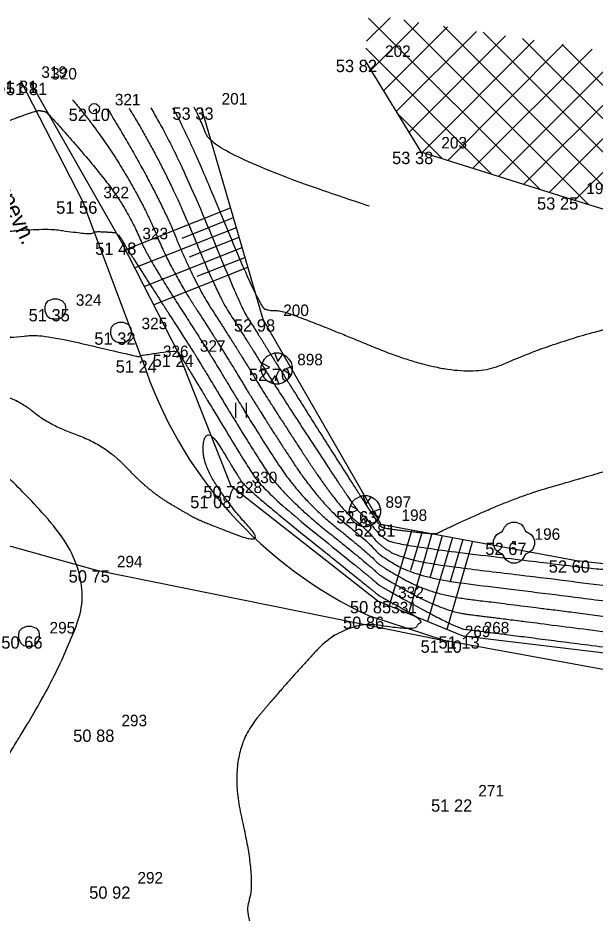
# Model space of a CAD drawing. Extents: x -704017 to -701500, y -1008977 to -1008450.
# Drawn here: x -703990.87 to -703976.82, y -1008655.12 to -1008633.32 of the extents above; entities that cross this region are included whole.
import ezdxf

# ---------------------------------------------------------------- set-up
doc = ezdxf.new("R2010")
doc.units = 0
for name, color, linetype in [('Z_body', 7, 'Continuous'), ('Z_body_cisla', 7, 'Continuous'), ('Z_body_vysky', 7, 'Continuous'), ('Z_komunikace', 7, 'Continuous'), ('Z_oploceni', 7, 'Continuous'), ('Z_popis', 7, 'Continuous'), ('Z_site_znaky_kanalizace', 7, 'Continuous'), ('Z_sloupky', 7, 'Continuous'), ('Z_teren_hrany_paty', 7, 'Continuous'), ('Z_vrstevnice_hlavni', 7, 'Continuous'), ('Z_vrstevnice_vedlejsi', 7, 'Continuous'), ('Z_zelen_jednotliva', 7, 'Continuous'), ('Z_zelen_souvisla_srafy', 7, 'Continuous')]:
    doc.layers.add(name, color=color, linetype=linetype)

# ---------------------------------------------------------------- blocks, each defined once
blk = doc.blocks.new('POINT_DISPLAY')
blk.add_line((0, 0), (0, 0))
blk = doc.blocks.new('Z306')
for p, q in [((-0.13, 0.17), (-0.13, -0.2)), ((0.13, 0.17), (0.13, -0.2))]:
    blk.add_line(p, q)
blk = doc.blocks.new('Z24')
for p, q in [((-0.23, 0.38), (-0.17, 0.45)), ((-0.17, 0.45), (-0.05, 0.5)), ((-0.05, 0.5), (0.05, 0.5)), ((0.05, 0.5), (0.17, 0.45)), ((0.17, 0.45), (0.23, 0.38)), ((-0.42, 0.2), (-0.28, 0.28)), ((-0.28, 0.28), (-0.23, 0.38)), ((0.23, 0.38), (0.28, 0.28)), ((0.28, 0.28), (0.42, 0.2)), ((-0.5, 0.05), (-0.47, 0.13)), ((-0.5, -0.05), (-0.5, 0.05)), ((-0.47, 0.13), (-0.42, 0.2)), ((-0.03, -0.03), (-0.03, 0.03)), ((-0.03, 0.03), (0.03, 0.03)), ((0.03, 0.03), (0.03, -0.03)), ((0.42, 0.2), (0.47, 0.13)), ((0.47, 0.13), (0.5, 0.05)), ((0.5, 0.05), (0.5, -0.05)), ((-0.45, -0.17), (-0.5, -0.05)), ((-0.38, -0.23), (-0.45, -0.17)), ((0.03, -0.03), (-0.03, -0.03)), ((0.45, -0.17), (0.38, -0.23)), ((0.5, -0.05), (0.45, -0.17)), ((-0.28, -0.28), (-0.38, -0.23)), ((-0.2, -0.42), (-0.28, -0.28)), ((-0.13, -0.47), (-0.2, -0.42)), ((0.2, -0.42), (0.13, -0.47)), ((0.28, -0.28), (0.2, -0.42)), ((0.38, -0.23), (0.28, -0.28)), ((-0.05, -0.5), (-0.13, -0.47)), ((0.05, -0.5), (-0.05, -0.5)), ((0.13, -0.47), (0.05, -0.5))]:
    blk.add_line(p, q)
blk = doc.blocks.new('Z23')
for p, q in [((-0.35, 0.13), (-0.3, 0.23)), ((-0.3, 0.23), (-0.23, 0.3)), ((-0.23, 0.3), (-0.13, 0.35)), ((-0.13, 0.35), (-0.05, 0.38)), ((-0.05, 0.38), (0.05, 0.38)), ((-0.05, 0.38), (0.03, 0.17)), ((0.03, 0.17), (0.15, 0.35)), ((0.05, 0.38), (0.15, 0.35)), ((0.15, 0.35), (0.23, 0.3)), ((0.23, 0.3), (0.3, 0.23)), ((0.3, 0.23), (0.35, 0.15)), ((-0.38, 0.05), (-0.35, 0.13)), ((-0.38, -0.05), (-0.38, 0.05)), ((-0.38, -0.05), (-0.17, 0.03)), ((-0.17, 0.03), (-0.35, 0.13)), ((0.38, 0.05), (0.17, -0.03)), ((0.35, 0.15), (0.38, 0.05)), ((0.38, 0.05), (0.38, -0.05)), ((-0.35, -0.13), (-0.38, -0.05)), ((-0.3, -0.23), (-0.35, -0.13)), ((-0.15, -0.35), (-0.03, -0.17)), ((-0.03, -0.17), (0.05, -0.38)), ((0.17, -0.03), (0.35, -0.15)), ((0.35, -0.15), (0.3, -0.23)), ((0.38, -0.05), (0.35, -0.15)), ((-0.23, -0.3), (-0.3, -0.23)), ((-0.15, -0.35), (-0.23, -0.3)), ((-0.05, -0.38), (-0.15, -0.35)), ((0.05, -0.38), (-0.05, -0.38)), ((0.15, -0.35), (0.05, -0.38)), ((0.23, -0.3), (0.15, -0.35)), ((0.3, -0.23), (0.23, -0.3))]:
    blk.add_line(p, q)
blk = doc.blocks.new('Z15')
blk.add_circle((0, 0), 0.125)
blk = doc.blocks.new('Z620')
for p, q in [((-0.17, 0.2), (-0.05, 0.25)), ((-0.05, 0.25), (0.05, 0.25)), ((0.05, 0.25), (0.17, 0.2)), ((-0.25, 0.05), (-0.23, 0.13)), ((-0.25, -0.05), (-0.25, 0.05)), ((-0.23, 0.13), (-0.17, 0.2)), ((0.17, 0.2), (0.23, 0.13)), ((0.23, 0.13), (0.25, 0.05)), ((0.25, 0.05), (0.25, -0.05)), ((-0.2, -0.17), (-0.25, -0.05)), ((-0.13, -0.23), (-0.2, -0.17)), ((0.2, -0.17), (0.13, -0.23)), ((0.25, -0.05), (0.2, -0.17)), ((-0.05, -0.25), (-0.13, -0.23)), ((0.05, -0.25), (-0.05, -0.25)), ((0.13, -0.23), (0.05, -0.25))]:
    blk.add_line(p, q)

msp = doc.modelspace()

# ---------------------------------------------------------------- linework, layer by layer
at = {"layer": 'Z_komunikace'}
for p, q in [((-703989.29, -1008637.79), (-703990.8, -1008634.85)), ((-703987.84, -1008641.66), (-703989.29, -1008637.79)), ((-703993.53, -1008645.49), (-703988.96, -1008646.77)), ((-703988.96, -1008646.77), (-703980.49, -1008648.48)), ((-703980.49, -1008648.48), (-703982.28, -1008647.9)), ((-703975.29, -1008649.43), (-703980.49, -1008648.48))]:
    msp.add_line(p, q, dxfattribs=at)
msp.add_arc((-703977.91, -1008638.41), 10.448, 198.1269, 245.2768, dxfattribs=at)
at = {"layer": 'Z_oploceni'}
for p, q in [((-703982.43, -1008634.34), (-703981.06, -1008636.58)), ((-703981.06, -1008636.58), (-703977.53, -1008637.69)), ((-703977.53, -1008637.69), (-703968.88, -1008640.38))]:
    msp.add_line(p, q, dxfattribs=at)
at = {"layer": 'Z_teren_hrany_paty'}
for p, q in [((-703988.34, -1008638.79), (-703990.56, -1008634.9)), ((-703986.41, -1008635.5), (-703984.91, -1008640.66)), ((-703985.7, -1008637.95), (-703988.25, -1008638.97)), ((-703985.63, -1008638.19), (-703986.88, -1008638.69)), ((-703985.56, -1008638.43), (-703988.02, -1008639.41)), ((-703985.49, -1008638.67), (-703986.7, -1008639.15)), ((-703986.94, -1008641.52), (-703988.34, -1008638.79)), ((-703985.42, -1008638.92), (-703987.79, -1008639.86)), ((-703985.35, -1008639.16), (-703986.51, -1008639.62)), ((-703985.28, -1008639.4), (-703987.56, -1008640.31)), ((-703984.91, -1008640.66), (-703982.03, -1008645.65)), ((-703985.68, -1008644.72), (-703986.94, -1008641.52)), ((-703982.11, -1008647.52), (-703985.68, -1008644.72)), ((-703982.03, -1008645.65), (-703977.27, -1008646.53)), ((-703981.28, -1008645.79), (-703981.83, -1008647.64)), ((-703980.79, -1008645.88), (-703981.36, -1008647.83)), ((-703981.03, -1008645.83), (-703981.31, -1008646.78)), ((-703980.29, -1008645.97), (-703980.9, -1008648.02)), ((-703980.54, -1008645.93), (-703980.83, -1008646.93)), ((-703979.8, -1008646.06), (-703980.43, -1008648.21)), ((-703980.04, -1008646.02), (-703980.35, -1008647.07)), ((-703977.27, -1008646.53), (-703966.65, -1008647.71)), ((-703980.03, -1008648.38), (-703982.11, -1008647.52)), ((-703970.25, -1008649.54), (-703980.03, -1008648.38))]:
    msp.add_line(p, q, dxfattribs=at)
at = {"layer": 'Z_vrstevnice_hlavni'}
for points in [[(-704009.834, -1008633.947), (-704008.639, -1008634.898), (-704007.097, -1008636.135), (-704003.977, -1008638.277), (-704003.231, -1008638.819), (-704001.631, -1008639.907), (-704000.867, -1008639.906), (-703997.17, -1008642.409), (-703994.823, -1008643.756), (-703994.703, -1008643.728), (-703993.348, -1008643.651), (-703992.995, -1008642.406), (-703992.399, -1008642.624), (-703992.166, -1008642.575), (-703991.657, -1008642.421), (-703990.877, -1008642.602), (-703990.087, -1008643.243), (-703988.737, -1008643.725), (-703987.719, -1008644.81), (-703986.755, -1008645.399), (-703986.308, -1008645.619), (-703984.807, -1008646.186), (-703985.704, -1008645.225), (-703986.427, -1008644.081), (-703986.268, -1008643.227), (-703985.558, -1008644.406), (-703985.308, -1008644.79), (-703982.136, -1008647.335), (-703982.104, -1008647.377), (-703980.996, -1008647.981), (-703981.138, -1008648.096), (-703981.236, -1008648.238), (-703982.91, -1008647.991), (-703984.29, -1008649.466), (-703985.783, -1008651.25), (-703985.074, -1008654.306), (-703985.408, -1008655.307), (-703984.22, -1008656.692), (-703983.2, -1008656.858), (-703982.505, -1008657.462), (-703981.889, -1008657.948), (-703981.945, -1008658.047), (-703982.027, -1008658.206), (-703982.128, -1008658.577), (-703982.119, -1008658.578), (-703981.97, -1008658.325), (-703981.459, -1008658.081), (-703981.513, -1008658.577), (-703981.415, -1008659.217), (-703981.332, -1008659.732), (-703980.559, -1008660.215), (-703980.405, -1008660.435), (-703979.463, -1008659.63), (-703979.059, -1008659.888), (-703977.693, -1008660.229), (-703973.778, -1008660.657)], [(-703989.544, -1008635.313), (-703988.902, -1008636.056), (-703987.798, -1008637.865), (-703987.151, -1008639.438), (-703986.053, -1008641.144), (-703985.706, -1008641.697), (-703984.977, -1008642.908), (-703983.536, -1008645.121), (-703982.31, -1008646.105), (-703982.063, -1008646.423), (-703981.066, -1008646.966), (-703978.397, -1008647.285), (-703974.283, -1008647.811), (-703967.8, -1008648.294), (-703964.571, -1008648.435), (-703963.695, -1008648.534), (-703960.428, -1008649.057), (-703958.881, -1008649.241), (-703956.672, -1008649.585), (-703952.719, -1008649.987), (-703950.97, -1008650.177), (-703947.545, -1008650.56), (-703946.3, -1008650.665), (-703945.127, -1008650.72), (-703944.757, -1008650.678), (-703944.314, -1008650.608), (-703943.915, -1008650.57), (-703942.581, -1008649.228), (-703940.433, -1008648.504), (-703938.207, -1008647.326), (-703935.424, -1008646.693), (-703932.523, -1008646.217), (-703931.63, -1008646.25), (-703927.689, -1008645.442), (-703927.074, -1008644.896), (-703916.856, -1008644.687)], [(-703987.108, -1008635.508), (-703986.754, -1008636.087), (-703984.996, -1008640.365), (-703984.718, -1008640.456), (-703984.363, -1008640.44), (-703980.087, -1008642.213), (-703978.073, -1008641.315), (-703975.667, -1008640.646), (-703970.073, -1008640.009)]]:
    msp.add_open_spline(points, degree=2, dxfattribs=at)
at = {"layer": 'Z_vrstevnice_vedlejsi'}
for points in [[(-704009.126, -1008633.406), (-704007.552, -1008634.66), (-704007.167, -1008634.969), (-704003.51, -1008637.478), (-704002.368, -1008638.123), (-704001.314, -1008638.122), (-703995.248, -1008642.229), (-703994.924, -1008642.415), (-703994.274, -1008642.264), (-703994.074, -1008642.252), (-703993.878, -1008641.56), (-703994.168, -1008638.078), (-703993.925, -1008637.137), (-703993.893, -1008637.055), (-703993.74, -1008636.777), (-703993.37, -1008636.731), (-703990.438, -1008635.556), (-703990.255, -1008635.594), (-703990.156, -1008635.607), (-703988.632, -1008637.37), (-703988.058, -1008638.31), (-703987.723, -1008639.127), (-703986.345, -1008641.268), (-703986.112, -1008641.639), (-703985.122, -1008643.283), (-703983.979, -1008645.038), (-703982.267, -1008646.413), (-703982.073, -1008646.661), (-703980.768, -1008647.373), (-703978.866, -1008647.6), (-703973.038, -1008648.345), (-703968.556, -1008648.679), (-703966.324, -1008648.776), (-703962.321, -1008649.227), (-703959.855, -1008649.621), (-703958.687, -1008649.76), (-703957.02, -1008650.02), (-703953.686, -1008650.359), (-703951.625, -1008650.597), (-703947.923, -1008651.012), (-703945.94, -1008651.178), (-703944.226, -1008651.1), (-703941.822, -1008651.374), (-703941.922, -1008651.3), (-703941.645, -1008651.165), (-703939.586, -1008650.472), (-703938.685, -1008649.995), (-703933.226, -1008648.754), (-703931.62, -1008648.491), (-703929.958, -1008648.552), (-703928.07, -1008648.165), (-703926.551, -1008646.817), (-703917.569, -1008646.632), (-703915.381, -1008647.242), (-703912.13, -1008647.203), (-703904.124, -1008647.793), (-703900.507, -1008648.357), (-703893.497, -1008649.743), (-703885.663, -1008650.277), (-703881.6, -1008650.754), (-703868.608, -1008650.262)], [(-704009.362, -1008633.586), (-704007.915, -1008634.739), (-704007.143, -1008635.358), (-704002.876, -1008638.286), (-704002.679, -1008638.43), (-704002.255, -1008638.718), (-704001.165, -1008638.717), (-703995.889, -1008642.289), (-703994.89, -1008642.862), (-703994.417, -1008642.752), (-703993.832, -1008642.719), (-703993.258, -1008640.696), (-703993.341, -1008639.701), (-703993.272, -1008639.432), (-703993.04, -1008638.835), (-703992.99, -1008638.745), (-703990.403, -1008638.423), (-703989.481, -1008638.539), (-703989.058, -1008638.588), (-703989.018, -1008638.516), (-703988.578, -1008638.54), (-703988.475, -1008638.554), (-703988.362, -1008638.685), (-703988.319, -1008638.754), (-703988.294, -1008638.815), (-703986.637, -1008641.391), (-703986.518, -1008641.581), (-703985.267, -1008643.657), (-703984.422, -1008644.955), (-703982.223, -1008646.72), (-703982.083, -1008646.9), (-703980.47, -1008647.779), (-703979.335, -1008647.914), (-703971.793, -1008648.878), (-703969.312, -1008649.063), (-703968.076, -1008649.117), (-703960.948, -1008649.919), (-703959.282, -1008650.186), (-703958.493, -1008650.28), (-703957.367, -1008650.455), (-703955.116, -1008650.684), (-703950.816, -1008651.182), (-703948.3, -1008651.463), (-703946.953, -1008651.576), (-703945.397, -1008651.505), (-703943.023, -1008651.703), (-703939.161, -1008651.987), (-703938.27, -1008652.079), (-703937.191, -1008652.194), (-703934.147, -1008651.524), (-703931.028, -1008650.815), (-703930.717, -1008650.764), (-703928.94, -1008650.83), (-703928.501, -1008650.751), (-703928.424, -1008650.713), (-703928.413, -1008650.708), (-703928.266, -1008650.724), (-703926.027, -1008648.737), (-703920.5, -1008648.624), (-703915.824, -1008649.925), (-703908.88, -1008649.843), (-703904.651, -1008650.155), (-703897.103, -1008651.333), (-703893.743, -1008651.997), (-703889.99, -1008652.252), (-703881.693, -1008653.228), (-703874.656, -1008652.961), (-703868.448, -1008652.365), (-703859.857, -1008652.906), (-703856.36, -1008653.001), (-703843.765, -1008653.766), (-703842.17, -1008653.801), (-703841.143, -1008653.824), (-703831.904, -1008654.28)], [(-704009.598, -1008633.766), (-704008.277, -1008634.819), (-704007.12, -1008635.746), (-704003.426, -1008638.282), (-704002.955, -1008638.624), (-704001.943, -1008639.313), (-704001.016, -1008639.312), (-703996.53, -1008642.349), (-703994.857, -1008643.309), (-703994.56, -1008643.24), (-703993.59, -1008643.185), (-703993.004, -1008641.121), (-703992.56, -1008641.283), (-703992.406, -1008640.907), (-703990.978, -1008641.146), (-703990.445, -1008640.984), (-703988.033, -1008641.546), (-703987.905, -1008641.575), (-703987.885, -1008641.539), (-703987.861, -1008641.54), (-703986.998, -1008641.406), (-703986.928, -1008641.515), (-703986.924, -1008641.522), (-703985.413, -1008644.031), (-703984.865, -1008644.873), (-703982.18, -1008647.028), (-703982.094, -1008647.138), (-703980.173, -1008648.185), (-703979.805, -1008648.229), (-703970.549, -1008649.412), (-703970.068, -1008649.448), (-703969.829, -1008649.458), (-703959.574, -1008650.612), (-703958.709, -1008650.75), (-703958.299, -1008650.799), (-703957.715, -1008650.89), (-703956.546, -1008651.009), (-703950.007, -1008651.766), (-703948.677, -1008651.914), (-703947.966, -1008651.974), (-703947.144, -1008651.937), (-703941.803, -1008652.381), (-703939.634, -1008652.541), (-703935.959, -1008652.918), (-703931.507, -1008653.392), (-703931.241, -1008653.334), (-703930.405, -1008652.729), (-703929.637, -1008652.341), (-703928.842, -1008651.433), (-703928.478, -1008651.254), (-703928.326, -1008651.185), (-703926.344, -1008651.403), (-703925.504, -1008650.658), (-703923.431, -1008650.615), (-703921.507, -1008651.151), (-703919.021, -1008652.183), (-703918.063, -1008652.174), (-703916.275, -1008652.677), (-703914.94, -1008652.463), (-703906.465, -1008652.493), (-703905.63, -1008652.483), (-703905.177, -1008652.517), (-703898.478, -1008653.562), (-703894.56, -1008654.198), (-703893.983, -1008654.291), (-703885.85, -1008655.223), (-703881.786, -1008655.701), (-703881.516, -1008655.691), (-703868.843, -1008654.474), (-703864.229, -1008654.765), (-703856.36, -1008654.976), (-703848.079, -1008655.479), (-703842.495, -1008655.602), (-703838.899, -1008655.683), (-703831.037, -1008656.071), (-703828.126, -1008656.326), (-703816.323, -1008657.511), (-703813.977, -1008657.649), (-703805.195, -1008657.724)], [(-703996.614, -1008653.997), (-703996.53, -1008653.954), (-703995.4, -1008652.79), (-703994.748, -1008653.468), (-703994.565, -1008653.661), (-703992.64, -1008658.49), (-703992.598, -1008656.799), (-703991.854, -1008653.994), (-703991.65, -1008652.14), (-703989.884, -1008649.309), (-703988.96, -1008646.77), (-703991.654, -1008643.898), (-703992.295, -1008643.669), (-703992.59, -1008643.726), (-703992.781, -1008643.766), (-703992.985, -1008643.692), (-703993.106, -1008644.118), (-703994.107, -1008644.174), (-703994.716, -1008644.242), (-703995.23, -1008643.95), (-703997.811, -1008642.469), (-704000.718, -1008640.501), (-704001.319, -1008640.502), (-704003.507, -1008639.013), (-704004.527, -1008638.272), (-704007.073, -1008636.524), (-704009.002, -1008634.978), (-704010.07, -1008634.127)], [(-703988.693, -1008635.526), (-703987.537, -1008637.421), (-703986.579, -1008639.75), (-703985.762, -1008641.021), (-703985.3, -1008641.755), (-703984.832, -1008642.534), (-703983.093, -1008645.204), (-703982.354, -1008645.798), (-703982.053, -1008646.184), (-703981.363, -1008646.56), (-703977.927, -1008646.97), (-703975.527, -1008647.277), (-703967.043, -1008647.91), (-703965.572, -1008647.974), (-703962.873, -1008648.321), (-703958.796, -1008648.865), (-703956.586, -1008648.506), (-703955.475, -1008648.39), (-703949.719, -1008647.438), (-703945.161, -1008647.87), (-703944.135, -1008648.531), (-703943.402, -1008647.939), (-703942.375, -1008646.905), (-703941.279, -1008646.536), (-703937.729, -1008644.657), (-703937.622, -1008644.632), (-703933.426, -1008643.944), (-703933.302, -1008643.948), (-703931.523, -1008643.583), (-703928.793, -1008643.072)], [(-703988.164, -1008635.52), (-703987.276, -1008636.976), (-703986.008, -1008640.062), (-703985.47, -1008640.897), (-703984.895, -1008641.813), (-703984.686, -1008642.159), (-703982.65, -1008645.287), (-703982.397, -1008645.49), (-703982.043, -1008645.946), (-703981.661, -1008646.154), (-703977.458, -1008646.656), (-703976.772, -1008646.743), (-703972.443, -1008647.066), (-703969.747, -1008647.327), (-703967.111, -1008646.193), (-703965.337, -1008645.561), (-703960.636, -1008644.491), (-703957.873, -1008644.043), (-703955.63, -1008643.808), (-703952.03, -1008643.609), (-703943.212, -1008644.531), (-703942.275, -1008644.62), (-703942.236, -1008644.645), (-703942.208, -1008644.623), (-703942.168, -1008644.583), (-703942.126, -1008644.569), (-703941.982, -1008644.492), (-703939.179, -1008642.975), (-703937.245, -1008642.629)], [(-703987.636, -1008635.514), (-703987.015, -1008636.531), (-703985.436, -1008640.373), (-703985.178, -1008640.774), (-703984.631, -1008641.646), (-703983.415, -1008643.583), (-703982.16, -1008645.543), (-703982.032, -1008645.707), (-703981.959, -1008645.748), (-703980.67, -1008645.901), (-703980.641, -1008645.843), (-703978.616, -1008644.94), (-703976.906, -1008644.464), (-703975.638, -1008644.064), (-703974.612, -1008645.108), (-703973.368, -1008645.311), (-703968.073, -1008643.034), (-703964.252, -1008641.672), (-703962.023, -1008640.719)], [(-703982.311, -1008637.906), (-703986.067, -1008636.679), (-703986.493, -1008635.642), (-703986.579, -1008635.502)]]:
    msp.add_open_spline(points, degree=2, dxfattribs=at)
at = {"layer": 'Z_zelen_souvisla_srafy'}
for p, q in [((-703982.38, -1008633.89), (-703981.81, -1008633.32)), ((-703982.33, -1008633.33), (-703978.16, -1008637.49)), ((-703982.28, -1008634.59), (-703981.11, -1008633.43)), ((-703981.47, -1008633.37), (-703976.98, -1008637.86)), ((-703981.97, -1008635.1), (-703980.41, -1008633.54)), ((-703981.66, -1008635.6), (-703979.7, -1008633.65)), ((-703980.51, -1008633.52), (-703975.8, -1008638.23)), ((-703979.54, -1008633.67), (-703974.62, -1008638.6)), ((-703981.35, -1008636.11), (-703979, -1008633.76)), ((-703981.02, -1008636.59), (-703978.3, -1008633.86)), ((-703978.58, -1008633.82), (-703973.44, -1008638.96)), ((-703982.4, -1008634.06), (-703979.35, -1008637.12)), ((-703980.4, -1008636.79), (-703977.59, -1008633.97)), ((-703979.79, -1008636.98), (-703976.89, -1008634.08)), ((-703977.62, -1008633.97), (-703972.26, -1008639.33)), ((-703979.17, -1008637.18), (-703976.18, -1008634.19)), ((-703978.55, -1008637.37), (-703975.48, -1008634.3)), ((-703977.93, -1008637.56), (-703974.78, -1008634.41)), ((-703977.31, -1008637.76), (-703974.07, -1008634.52)), ((-703981.63, -1008635.65), (-703980.54, -1008636.74))]:
    msp.add_line(p, q, dxfattribs=at)

# ---------------------------------------------------------------- block references
at = {"layer": 'Z_body'}
for p in [(-703982.43, -1008634.34), (-703990.8, -1008634.85), (-703990.56, -1008634.9), (-703989.01, -1008635.53), (-703986.41, -1008635.5), (-703981.06, -1008636.58), (-703989.29, -1008637.79), (-703977.53, -1008637.69), (-703988.34, -1008638.79), (-703989.96, -1008640.41), (-703984.91, -1008640.66), (-703988.36, -1008640.98), (-703986.94, -1008641.52), (-703987.84, -1008641.66), (-703984.57, -1008641.86), (-703985.68, -1008644.72), (-703986.05, -1008644.96), (-703982.42, -1008645.33), (-703982.03, -1008645.65), (-703978.79, -1008646.1), (-703977.27, -1008646.53), (-703988.96, -1008646.77), (-703982.11, -1008647.52), (-703982.28, -1008647.9), (-703990.6, -1008648.38), (-703980.49, -1008648.48), (-703980.03, -1008648.38), (-703988.85, -1008650.65), (-703980.16, -1008652.35), (-703988.46, -1008654.47)]:
    msp.add_blockref('POINT_DISPLAY', p, dxfattribs=at)
at = {"layer": 'Z_popis'}
msp.add_blockref('Z306', (-703985.44, -1008642.86), dxfattribs=at)
at = {"layer": 'Z_site_znaky_kanalizace'}
for p in [(-703989.96, -1008640.41), (-703988.36, -1008640.98), (-703990.6, -1008648.38)]:
    msp.add_blockref('Z620', p, dxfattribs=at)
at = {"layer": 'Z_sloupky'}
msp.add_blockref('Z15', (-703989.01, -1008635.53), dxfattribs=at)
at = {"layer": 'Z_zelen_jednotliva'}
for name, p in [('Z23', (-703984.57, -1008641.86)), ('Z23', (-703982.42, -1008645.33)), ('Z24', (-703978.79, -1008646.1))]:
    msp.add_blockref(name, p, dxfattribs=at)

# ---------------------------------------------------------------- texts
at = {"layer": 'Z_body_cisla'}
for s, p in [('202', (-703981.93, -1008634.27)), ('319', (-703990.3, -1008634.78)), ('320', (-703990.06, -1008634.82)), ('321', (-703988.51, -1008635.45)), ('201', (-703985.91, -1008635.43)), ('203', (-703980.56, -1008636.5)), ('197', (-703977.03, -1008637.61)), ('322', (-703988.79, -1008637.71)), ('323', (-703987.84, -1008638.71)), ('324', (-703989.46, -1008640.33)), ('200', (-703984.41, -1008640.58)), ('325', (-703987.86, -1008640.9)), ('326', (-703987.34, -1008641.58)), ('327', (-703986.44, -1008641.45)), ('898', (-703984.07, -1008641.78)), ('330', (-703985.18, -1008644.65)), ('328', (-703985.55, -1008644.89)), ('897', (-703981.92, -1008645.25)), ('198', (-703981.53, -1008645.57)), ('196', (-703978.29, -1008646.03)), ('294', (-703988.46, -1008646.7)), ('332', (-703981.61, -1008647.45)), ('331', (-703981.78, -1008647.82)), ('295', (-703990.1, -1008648.31)), ('268', (-703979.53, -1008648.31)), ('269', (-703979.99, -1008648.4)), ('293', (-703988.35, -1008650.57)), ('271', (-703979.66, -1008652.28)), ('292', (-703987.96, -1008654.4))]:
    msp.add_text(s, height=0.28, dxfattribs=at).set_placement(p)
at = {"layer": 'Z_body_vysky'}
for s, p in [('53 82', (-703983.13, -1008634.64)), ('51 81', (-703991.4, -1008635.15)), ('51 81', (-703991.16, -1008635.2)), ('52 10', (-703989.635, -1008635.83)), ('53 33', (-703987.11, -1008635.8)), ('53 38', (-703981.76, -1008636.88)), ('51 56', (-703989.94, -1008638.09)), ('53 25', (-703978.23, -1008637.99)), ('51 48', (-703988.99, -1008639.09)), ('51 35', (-703990.61, -1008640.71)), ('52 98', (-703985.61, -1008640.96)), ('51 32', (-703989.01, -1008641.28)), ('51 24', (-703987.59, -1008641.82)), ('51 24', (-703988.49, -1008641.96)), ('52 70', (-703985.245, -1008642.16)), ('50 79', (-703986.355, -1008645.02)), ('51 08', (-703986.675, -1008645.26)), ('52 63', (-703983.12, -1008645.63)), ('52 81', (-703982.68, -1008645.95)), ('52 67', (-703979.49, -1008646.4)), ('52 60', (-703977.945, -1008646.83)), ('50 75', (-703989.635, -1008647.07)), ('50 85', (-703982.785, -1008647.82)), ('50 86', (-703982.955, -1008648.2)), ('50 66', (-703991.275, -1008648.68)), ('51 10', (-703981.065, -1008648.78)), ('51 13', (-703980.63, -1008648.68)), ('50 88', (-703989.525, -1008650.95)), ('51 22', (-703980.81, -1008652.65)), ('50 92', (-703989.135, -1008654.77))]:
    msp.add_text(s, height=0.3, dxfattribs=at).set_placement(p)
at = {"layer": 'Z_popis'}
msp.add_text('komunikace - zpevn.', height=0.4, rotation=295.2, dxfattribs=at).set_placement((-703992.84, -1008634.44))

doc.saveas('drawing.dxf')
